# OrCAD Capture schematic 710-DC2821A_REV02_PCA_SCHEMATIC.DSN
size Custom; note: 42VIN COMPACT ISOLATED FLYBACK CONVERTER
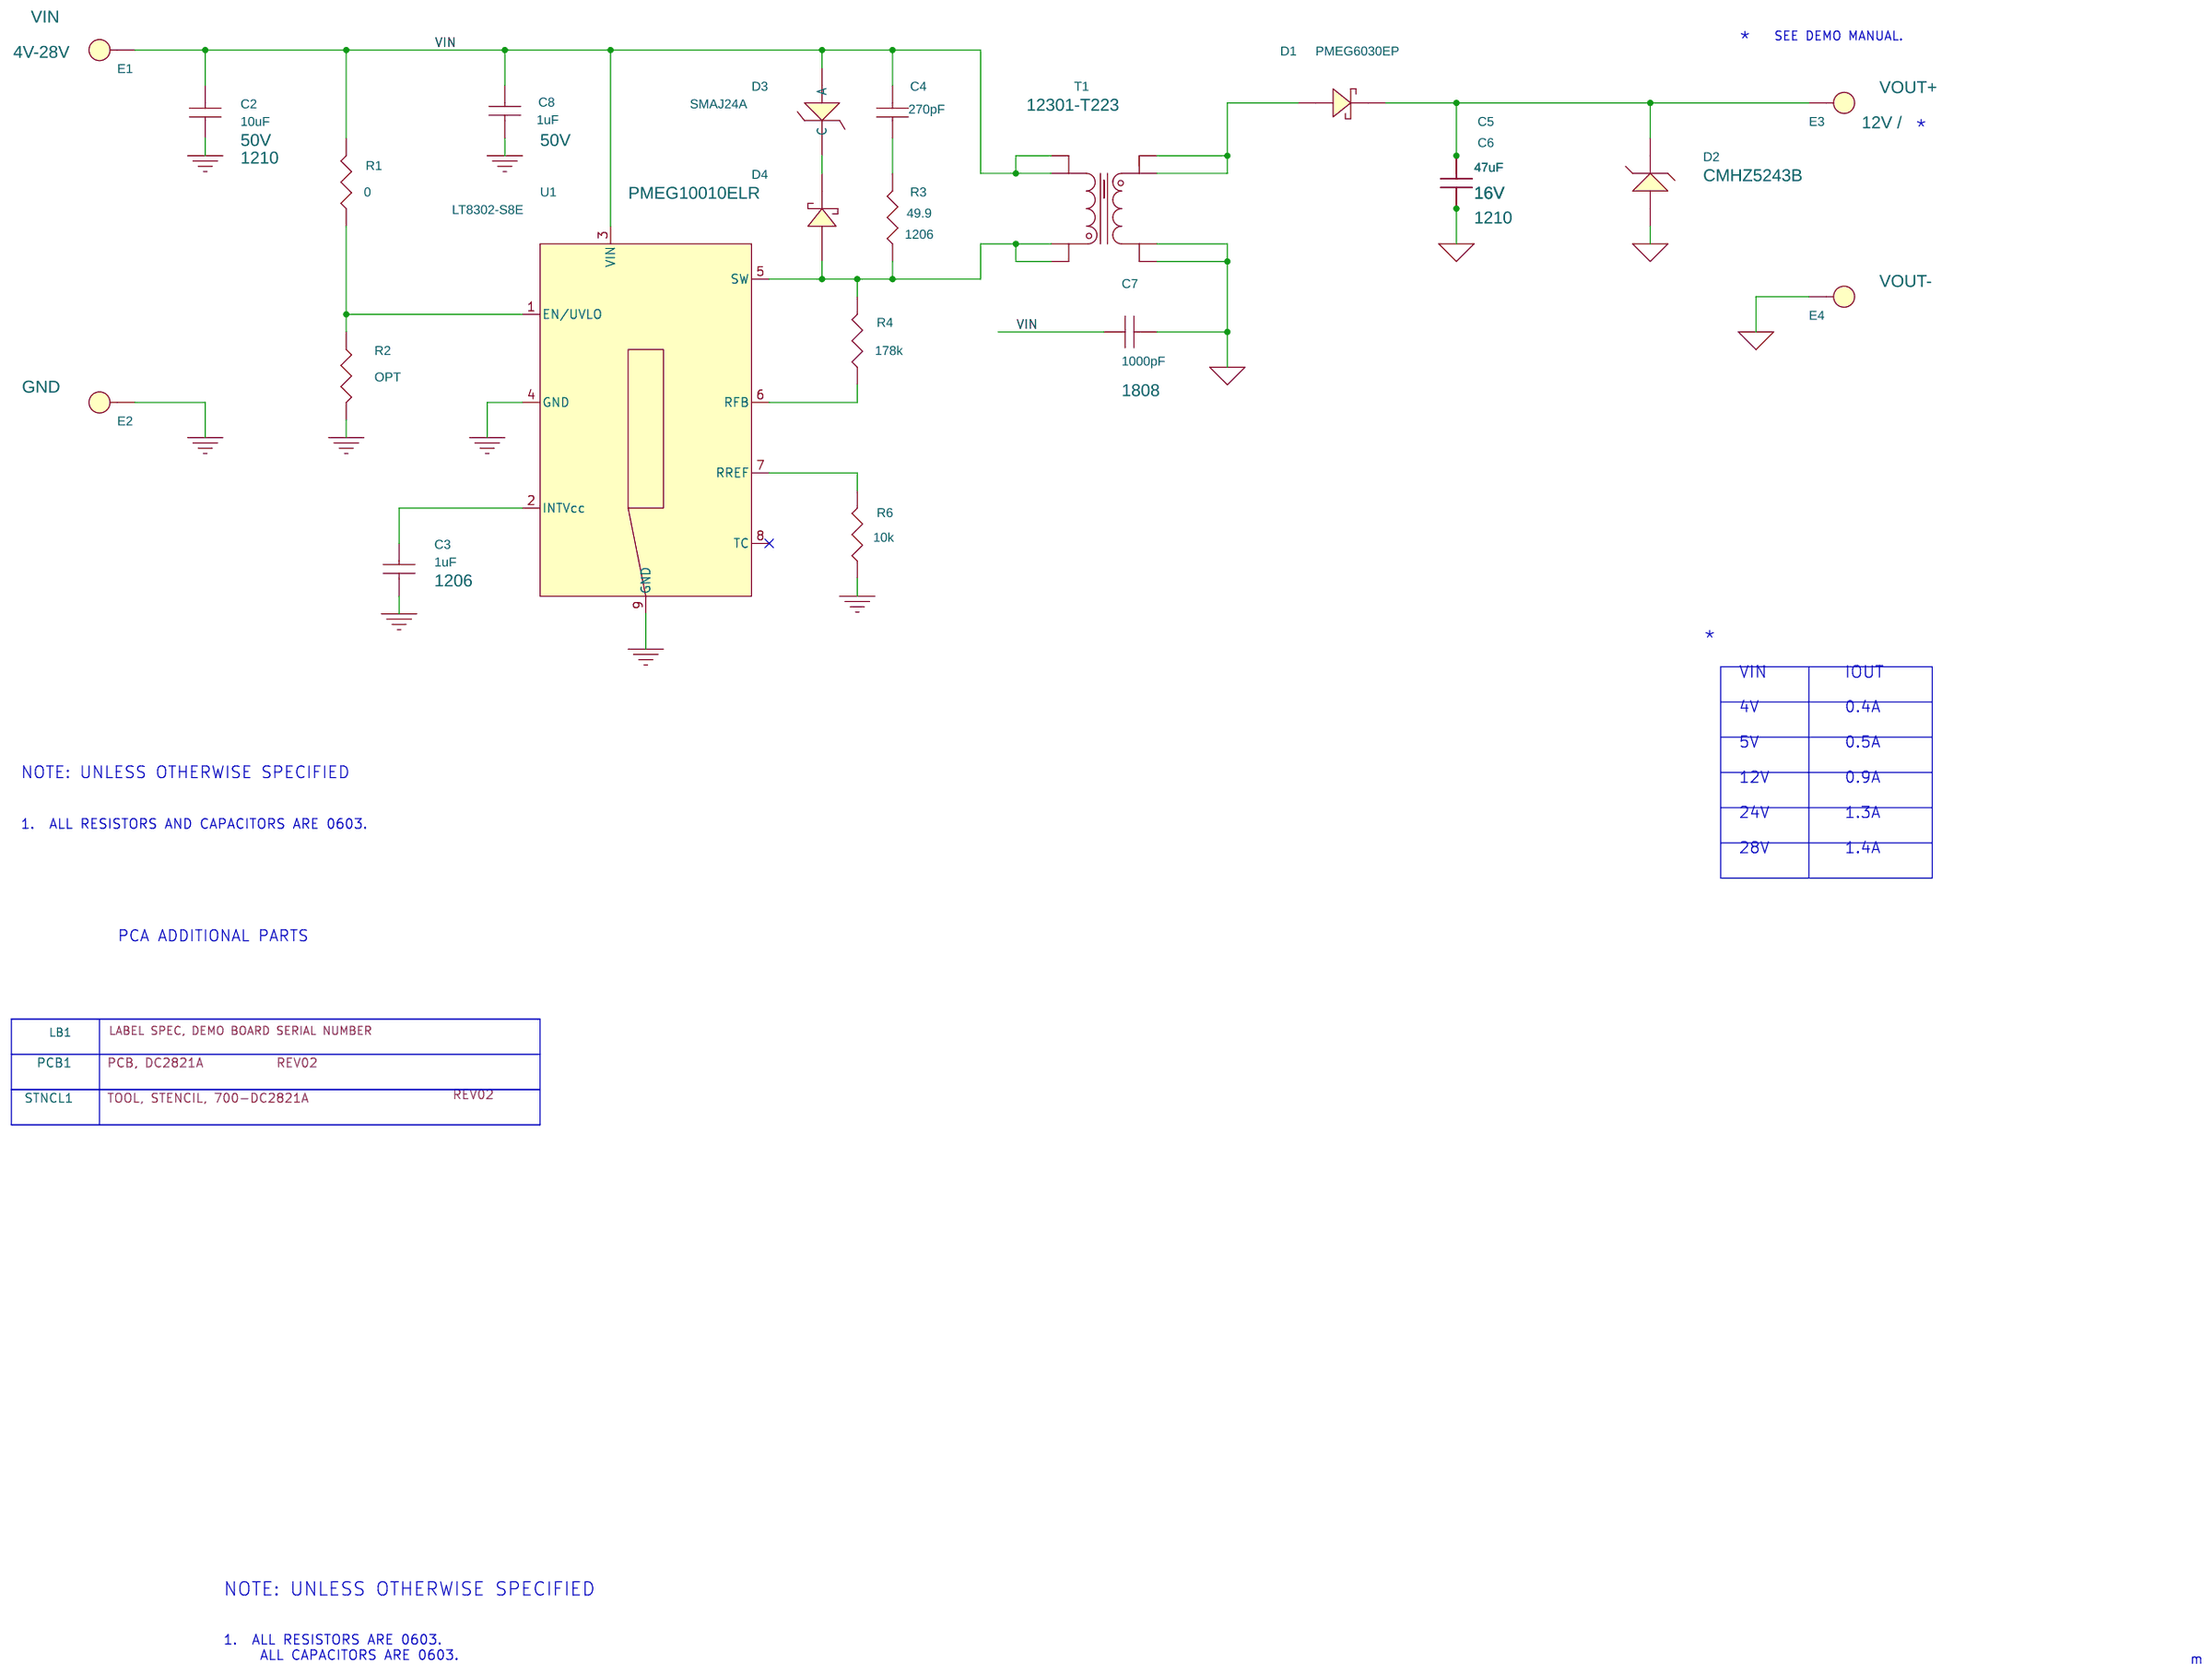
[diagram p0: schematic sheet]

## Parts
C2  10uF  [CC1210N]
C3  1uF  [CC1206N]
C4  270pF  [CC0603N]
C5  47uF  [CC1210N]
C6  47uF  [CC1210N]
C7  1000pF  [CC1808N]
C8  1uF  [CC0603N]
D1  PMEG6030EP,115  [SOD-128N]
D2  CMHZ5243B  [SOD-123N]
D3  SMAJ24A  [SMA-N]
D4  PMEG10010ELR  [NXP-SOD-123W]
E1  TEST POINT  [MILLMAX2308]
E2  TEST POINT  [MILLMAX2308]
E3  TEST POINT  [MILLMAX2308]
E4  TEST POINT  [MILLMAX2308]
LB1  LABEL  [895-0154_REV01]
PCB1  PCB, DC2821A
R1  0  [CR0603N]
R2  OPT  [CR0603N]
R3  49.9  [CR1206N]
R4  178k  [CR0603N]
R6  10k  [CR0603N]
STNCL1  TOOL, STENCIL, 700-DC2821A
T1  12301-T223  [SUMIDA-CEEH158]
U1  LT8302-S8E  [LTC-S8E-8-1857]

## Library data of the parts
C2 = CAP: CAP.,10uF,X7R,50V,10%,1210, NO SUBS. ALLOWED; CLASS: DISCRETE; Dielectric Type: X7R; Manufacturer: MURATA; Manufacturer PN: GRM32ER71H106KA12L; PART_NUMBER: 150-3043; Package Size: 1210; Package Type: SMD; Rated Voltage: 50V; Tolerance: 10%; UserField01: NO SUBS. ALLOWED
C3 = CAP: CAP.,1uF,X7R,50V,10%,1206; CLASS: DISCRETE; Dielectric Type: X7R; Manufacturer: MURATA; Manufacturer PN: GRM31CR71H105KA61L; PART_NUMBER: 150-3089; Package Size: 1206; Rated Voltage: 50V; Tolerance: 10%
C4 = CAP: CAP.,270pF,C0G,100V,5%,0603; CLASS: DISCRETE; COMPFIXED: 25V; Dielectric Type: C0G; FPLIST: CC0603N,CC0603L,CC0603M; Manufacturer: MURATA; Manufacturer PN: GRM1885C2A271JA01D; PART_NUMBER: 150-2534; Package Size: 0603; Rated Voltage: 100V; Tolerance: 5%
C5 C6 = CAP: CAP.,47uF,X5R,16V,10%,1210; CLASS: DISCRETE; Dielectric Type: X5R; FPLIST: CC1210N,CC1210L,CC1210M; Manufacturer: MURATA; Manufacturer PN: GRM32ER61C476KE15L; PART_NUMBER: 150-2352; Package Size: 1210; Rated Voltage: 16V; Tolerance: 10%
C7 = CAP: CAP.,1000pF,X7R,250V,10%,1808; CLASS: DISCRETE; Dielectric Type: X7R; FPLIST: CC1808N,CC1808L,CC1808M; Manufacturer: MURATA; Manufacturer PN: GA342DR7GF102KW02L; PART_NUMBER: 150-2527; Package Size: 1808; Rated Voltage: 250V; Tolerance: 10%
C8 = CAP: CAP.,1uF,X7R,50V,10%,0603; CLASS: DISCRETE; Dielectric Type: X7R; FPLIST: CC0603N,CC0603L,CC0603M; Manufacturer: TAIYO YUDEN; Manufacturer PN: UMK107AB7105KA-T; PART_NUMBER: 150-2333; Package Size: 0603; Rated Voltage: 50V; Tolerance: 10%; UserField01: OPTION
D1 = DIODE_SCHOTTKY_A_ALT: DIODE,SCHOTTKY,60V,3A,SOD-128,AEC-Q101; BOM Notes: P/N TBD; CLASS: DISCRETE; FPLIST: SOD-128N,SOD-128L,SOD-128M; Manufacturer: NEXPERIA; PART_FIELD_01: PMEG6030EP; PART_NUMBER: 210-0239; Package Size: SOD-128; Package Type: SOD-128
D2 = ZENER_ALT: DIODE,ZENER,13V,500mW,SOD-123-2; CLASS: DISCRETE; Manufacturer: CENTRAL SEMI.; Manufacturer PN: CMHZ5243B TR PBFREE; PART_NUMBER: 210-0324; Package Type: SOD-123-2; Rated Voltage: 13V
D3 = DIODE_TVS_B: DIODE,TVS,24V,400W,SMA-2; CLASS: DISCRETE; Manufacturer: DIODES INC.; Manufacturer PN: SMAJ24A-13-F; PART_NUMBER: 210-0121; Package Size: SMA; Package Type: SMA-2
D4 = DIODE_SCHOTTKY_A_ALT: DIODE,SCHOTTKY,100V,1A,SOD-123W-2,AEC-Q101; CLASS: DISCRETE; Manufacturer: NEXPERIA; PART_NUMBER: 210-0325; Package Type: SOD-123W-2; Rated Voltage: 100V
E1 = TEST_POINT_.156_MILL-MAX_2308: TEST POINT,TURRET,0.064",MTG. HOLE; ALT_SYMBOLS: null; CLASS: IO; Manufacturer: MILL-MAX; Manufacturer PN: 2308-2-00-80-00-00-07-0; PART_FIELD_1: VIN; PART_FIELD_2: 4V-28V; PART_NUMBER: 260-0004; Rated Power: null
E2 = TEST_POINT_.156_MILL-MAX_2308: TEST POINT,TURRET,0.064",MTG. HOLE; ALT_SYMBOLS: null; CLASS: IO; Manufacturer: MILL-MAX; Manufacturer PN: 2308-2-00-80-00-00-07-0; PART_FIELD_1: GND; PART_NUMBER: 260-0004; Rated Power: null
E3 = TEST_POINT_.156_MILL-MAX_2308: TEST POINT,TURRET,0.064",MTG. HOLE; ALT_SYMBOLS: null; CLASS: IO; Manufacturer: MILL-MAX; Manufacturer PN: 2308-2-00-80-00-00-07-0; PART_FIELD_1: VOUT+; PART_FIELD_2: 12V /; PART_NUMBER: 260-0004; Rated Power: null
E4 = TEST_POINT_.156_MILL-MAX_2308: TEST POINT,TURRET,0.064",MTG. HOLE; ALT_SYMBOLS: null; CLASS: IO; Manufacturer: MILL-MAX; Manufacturer PN: 2308-2-00-80-00-00-07-0; PART_FIELD_1: VOUT-; PART_NUMBER: 260-0004; Rated Power: null
LB1 = BLANK_LABEL: LABEL SPEC, DEMO BOARD SERIAL NUMBER; Manufacturer: BRADY; Manufacturer PN: THT-96-717-10; PART_NUMBER: 895-0154
PCB1 = BLANK_PCB_PART: BOM Notes: REV02; CLASS: DISCRETE; Manufacturer: EAGLE ELECTRONICS INC.; Manufacturer PN: 600-DC2821A; PART_NUMBER: 600-DC2821A
R1 = RES: RES.,0 OHM,1/10W,0603; CLASS: DISCRETE; FPLIST: CR0603N,CR0603L,CR0603M; Manufacturer: VISHAY; Manufacturer PN: CRCW06030000Z0EA; PART_NUMBER: 100-0009; Package Size: 0603; Rated Power: 1/10W
R2 = RES: RES., OPTION, 0603; CLASS: DISCRETE; FPLIST: CR0603N,CR0603L,CR0603M; PART_NUMBER: 100-2374; Package Size: 0603
R3 = RES: RES.,49.9 OHMS,1%,1/4W,1206; CLASS: DISCRETE; FPLIST: CR1206N,CR1206L,CR1206M; Manufacturer: NIC; Manufacturer PN: NRC12F49R9TRF; PART_NUMBER: 100-2791; Package Size: 1206; Rated Power: 1/4W; Temperature Coefficient: 100ppm/C; Tolerance: 1%
R4 = RES: RES.,AEC-Q200,178k OHMS,1%,1/10W,0603; BOM Notes: R4 P/N TBD; CLASS: DISCRETE; FPLIST: CR0603N,CR0603L,CR0603M; Manufacturer: VISHAY; Manufacturer PN: CRCW0603178KFKEA; PART_FIELD_01: TBD; PART_NUMBER: 100-1014; Package Size: 0603; Rated Power: 1/10W; Temperature Coefficient: 100ppm; Tolerance: 1%
R6 = RES: RES.,10k OHMS,0.1%,1/10W,0603; CLASS: DISCRETE; FPLIST: CR0603N,CR0603L,CR0603M; Manufacturer: VISHAY; Manufacturer PN: TNPW060310K0BEEA; PART_NUMBER: 100-2059; Package Size: 0603; Rated Power: 1/10W; Temperature Coefficient: +/-100PPM; Tolerance: 0.1%
STNCL1 = BLANK_STENCIL_PART: BOM Notes: REV02; CLASS: DISCRETE; Manufacturer: LINEAR TECH.; Manufacturer PN: 830-DC2821A; PART_NUMBER: 830-DC2821A
T1 = SUMIDA-CEEH158: TRANSFORMER,Np: 4-28Vin, Ns: 12v with 1.5A,17x16mm SMD; CLASS: DISCRETE; Manufacturer: SUMIDA; PART_NUMBER: 410-0104
U1 = LT8302_8304-S8E-X: IC,MICROPOWER FLYBACK CONVERTER,S8E, SO-8; CLASS: IC; Manufacturer: LINEAR TECH.; Manufacturer PN: LT8302ES8E#PBF; PART_NUMBER: LT8302ES8E#PBF; Package Type: S8E, SO-8

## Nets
GND: C2.1 C3.2 C8.2 E2.1(A) R2.1 R6.2 U1.4(GND) U1.9(GND)
GND_SIGNAL: C5.1 C6.1 C7.2 D2.2(A) E4.1(A) T1.6 T1.7
VIN: C2.2 C4.2 C7.1 C8.1 D3.2(A) E1.1(A) R1.1 T1.4 T1.5 U1.3(VIN)
N16958277: C5.2 C6.2 D1.1(C) D2.1(C) E3.1(A)
N16958357: D4.2(A) R3.2 R4.1 T1.1 T1.2 U1.5(SW)
N16958363: D1.2(A) T1.9 T1.10
N16958426: R4.2 U1.6(RFB)
N16958468: R6.1 U1.7(RREF)
N16958490: C3.1 U1.2(INTVcc)
N16958528: R1.2 R2.2 U1.1(EN/UVLO)
N16973060: C4.1 R3.1
N16997214: D3.1(C) D4.1(C)

Not connected (* = marked no-connect by the designer): U1 8(TC)*

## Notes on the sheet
- *
- SEE DEMO MANUAL.
- *
- *
- VIN
- IOUT
- 4V
- 0.4A
- 5V
- 0.5A
- NOTE: UNLESS OTHERWISE SPECIFIED
- 12V
- 0.9A
- 1.  ALL RESISTORS AND CAPACITORS ARE 0603.
- 24V
- 1.3A
- 28V
- 1.4A
- PCA ADDITIONAL PARTS
- NOTE: UNLESS OTHERWISE SPECIFIED
- 1.  ALL RESISTORS ARE 0603.
       ALL CAPACITORS ARE 0603.
- m
